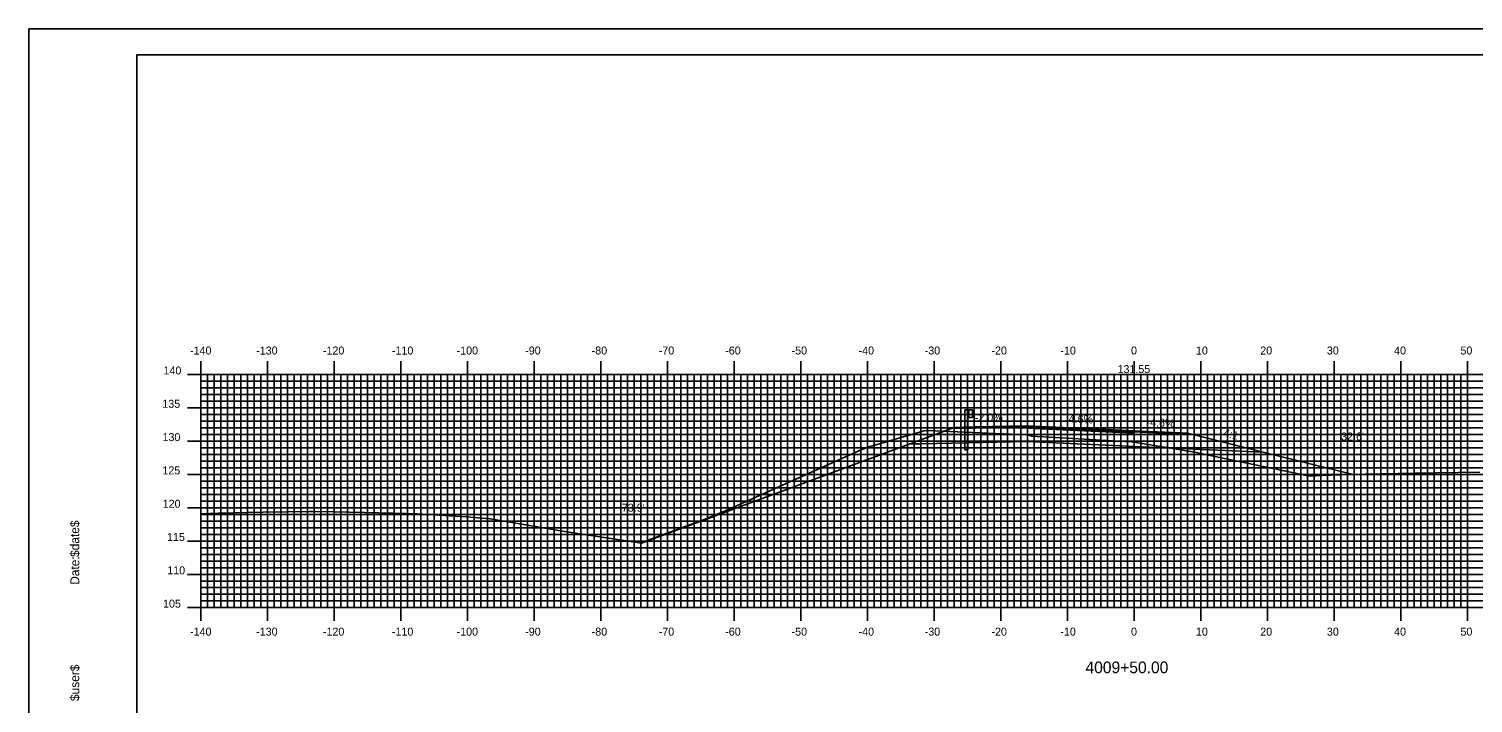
# Model space of a CAD drawing. Extents: x 852147 to 852490, y 364661 to 364881.
# Drawn here: x 852147 to 852363.6, y 364780 to 364881.3 of the extents above; entities that cross this region are included whole.
import ezdxf

# ---------------------------------------------------------------- set-up
doc = ezdxf.new("R2010")
doc.units = 0
for name, color, linetype in [('ANNOTATION', 7, 'Continuous'), ('BORDER', 7, 'Continuous'), ('D_Guardrail_Beam_Lt', 7, 'Continuous'), ('D_Roadway_Centerline_Text', 7, 'Continuous'), ('D_Roadway_Edge_Shoulder', 7, 'Continuous'), ('D_Roadway_Edge_TW', 7, 'Continuous'), ('D_Roadway_Pavement', 7, 'Continuous'), ('D_Roadway_SlopeLines', 7, 'Continuous'), ('D_Roadway_SubGrade', 7, 'Continuous'), ('D_Text_Standard', 7, 'Continuous'), ('H_V ANNOTATION', 7, 'Continuous'), ('M_Roadway_Centerline', 7, 'Continuous'), ('MAJOR', 7, 'Continuous'), ('MINOR', 7, 'Continuous'), ('PLOT BOUNDARY', 7, 'Continuous'), ('S_Roadway_Centerline', 7, 'Continuous')]:
    doc.layers.add(name, color=color, linetype=linetype)

msp = doc.modelspace()

# ---------------------------------------------------------------- linework, layer by layer
at = {"layer": 'ANNOTATION'}
for p, q in [((852285.76, 364821.43), (852238.86, 364804.07)), ((852280.84, 364818.98), (852279.02, 364818.94))]:
    msp.add_line(p, q, dxfattribs=at)
at = {"layer": 'BORDER'}
msp.add_lwpolyline([(852163.16, 364667.37), (852483.16, 364667.37), (852483.16, 364877.37), (852163.16, 364877.37)], close=True, dxfattribs=at)
at = {"layer": 'D_Guardrail_Beam_Lt'}
for p, q in [((852287.33, 364824.08), (852287.33, 364818.08)), ((852287.8, 364824.08), (852287.33, 364824.08)), ((852288.48, 364824.08), (852287.8, 364824.08)), ((852287.8, 364824.08), (852287.8, 364822.91)), ((852287.86, 364824.08), (852287.86, 364822.91)), ((852287.96, 364824.08), (852287.96, 364822.91)), ((852288.48, 364822.91), (852288.48, 364824.08)), ((852288.48, 364823.99), (852288.56, 364823.98)), ((852288.49, 364823.53), (852288.49, 364823.46)), ((852288.72, 364823.73), (852288.52, 364823.59)), ((852288.52, 364823.39), (852288.72, 364823.26)), ((852288.57, 364823.97), (852288.72, 364823.87)), ((852288.72, 364823.11), (852288.57, 364823.01)), ((852287.8, 364822.91), (852288.48, 364822.91)), ((852287.82, 364818.08), (852287.82, 364822.91)), ((852288.56, 364823.01), (852288.48, 364822.99)), ((852287.82, 364818.08), (852287.33, 364818.08))]:
    msp.add_line(p, q, dxfattribs=at)
for centre, major_axis, start_param, end_param in [((852288.57, 364823.53), (-0.0789, 0), 5.323254, 6.283185), ((852288.57, 364823.46), (-0.0789, 0), 6.283185, 7.243116), ((852288.55, 364823.94), (0.0417, 0), 0.959931, 1.376053), ((852288.67, 364823.8), (0.0877, 0), 5.323254, 7.243116), ((852288.67, 364823.19), (0.0877, 0), 5.323254, 7.243116), ((852288.55, 364823.05), (0.0417, 0), 4.907132, 5.323254)]:
    msp.add_ellipse(centre, major_axis=major_axis, ratio=0.995501, start_param=start_param, end_param=end_param, dxfattribs=at)
at = {"layer": 'D_Roadway_Edge_Shoulder'}
msp.add_lwpolyline([(852296.76, 364821.65), (852288.76, 364821.49), (852288.76, 364821.49), (852285.76, 364821.43), (852285.76, 364821.27), (852296.76, 364821.46)], close=True, dxfattribs=at)
at = {"layer": 'D_Roadway_Edge_TW'}
msp.add_line((852312.76, 364820.92), (852320.76, 364820.55), dxfattribs=at)
msp.add_lwpolyline([(852296.76, 364821.65), (852312.76, 364820.92), (852312.76, 364820.75), (852296.76, 364821.47)], close=True, dxfattribs=at)
msp.add_lwpolyline([(852312.76, 364820.75), (852320.76, 364820.38), (852320.76, 364820.55)], dxfattribs=at)
at = {"layer": 'D_Roadway_Pavement'}
msp.add_lwpolyline([(852296.76, 364821.47), (852312.76, 364820.75), (852312.76, 364820.58), (852296.76, 364821.3)], close=True, dxfattribs=at)
for points in [[(852296.76, 364821.47), (852296.76, 364821.3)], [(852312.76, 364820.75), (852312.76, 364820.58)], [(852312.76, 364820.75), (852312.76, 364820.58)]]:
    msp.add_lwpolyline(points, dxfattribs=at)
at = {"layer": 'D_Roadway_SlopeLines'}
msp.add_lwpolyline([(852320.76, 364820.55), (852332.29, 364817.67), (852345.39, 364814.39)], dxfattribs=at)
at = {"layer": 'D_Roadway_SubGrade'}
msp.add_line((852312.76, 364818.58), (852332.05, 364817.72), dxfattribs=at)
msp.add_lwpolyline([(852280.84, 364818.98), (852296.76, 364819.29), (852296.76, 364821.29), (852296.76, 364821.46), (852285.76, 364821.27), (852285.76, 364821.43)], dxfattribs=at)
msp.add_lwpolyline([(852296.76, 364821.3), (852312.76, 364820.58), (852312.76, 364818.58), (852296.76, 364819.3)], close=True, dxfattribs=at)
at = {"layer": 'MAJOR'}
for p, q in [((852172.76, 364831.37), (852172.76, 364829.37)), ((852182.76, 364831.37), (852182.76, 364829.37)), ((852192.76, 364831.37), (852192.76, 364829.37)), ((852202.76, 364831.37), (852202.76, 364829.37)), ((852212.76, 364831.37), (852212.76, 364829.37)), ((852222.76, 364831.37), (852222.76, 364829.37)), ((852232.76, 364831.37), (852232.76, 364829.37)), ((852242.76, 364831.37), (852242.76, 364829.37)), ((852252.76, 364831.37), (852252.76, 364829.37)), ((852262.76, 364831.37), (852262.76, 364829.37)), ((852272.76, 364831.37), (852272.76, 364829.37)), ((852282.76, 364831.37), (852282.76, 364829.37)), ((852292.76, 364831.37), (852292.76, 364829.37)), ((852302.76, 364831.37), (852302.76, 364829.37)), ((852312.76, 364831.37), (852312.76, 364829.37)), ((852322.76, 364831.37), (852322.76, 364829.37)), ((852332.76, 364831.37), (852332.76, 364829.37)), ((852342.76, 364831.37), (852342.76, 364829.37)), ((852352.76, 364831.37), (852352.76, 364829.37)), ((852362.76, 364831.37), (852362.76, 364829.37)), ((852170.75, 364829.37), (852172.76, 364829.37)), ((852172.76, 364829.37), (852452.76, 364829.37)), ((852172.76, 364794.37), (852172.76, 364829.37)), ((852172.76, 364794.37), (852172.76, 364829.37)), ((852172.76, 364829.37), (852452.76, 364829.37)), ((852182.76, 364794.37), (852182.76, 364829.37)), ((852192.76, 364794.37), (852192.76, 364829.37)), ((852202.76, 364794.37), (852202.76, 364829.37)), ((852212.76, 364794.37), (852212.76, 364829.37)), ((852222.76, 364794.37), (852222.76, 364829.37)), ((852232.76, 364794.37), (852232.76, 364829.37)), ((852242.76, 364794.37), (852242.76, 364829.37)), ((852252.76, 364794.37), (852252.76, 364829.37)), ((852262.76, 364794.37), (852262.76, 364829.37)), ((852272.76, 364794.37), (852272.76, 364829.37)), ((852282.76, 364794.37), (852282.76, 364829.37)), ((852292.76, 364794.37), (852292.76, 364829.37)), ((852302.76, 364794.37), (852302.76, 364829.37)), ((852312.76, 364794.37), (852312.76, 364829.37)), ((852322.76, 364794.37), (852322.76, 364829.37)), ((852332.76, 364794.37), (852332.76, 364829.37)), ((852342.76, 364794.37), (852342.76, 364829.37)), ((852352.76, 364794.37), (852352.76, 364829.37)), ((852362.76, 364794.37), (852362.76, 364829.37)), ((852170.75, 364824.37), (852172.76, 364824.37)), ((852172.76, 364824.37), (852452.76, 364824.37)), ((852170.75, 364819.37), (852172.76, 364819.37)), ((852172.76, 364819.37), (852452.76, 364819.37)), ((852170.75, 364814.37), (852172.76, 364814.37)), ((852172.76, 364814.37), (852452.76, 364814.37)), ((852170.75, 364809.37), (852172.76, 364809.37)), ((852172.76, 364809.37), (852452.76, 364809.37)), ((852170.75, 364804.37), (852172.76, 364804.37)), ((852172.76, 364804.37), (852452.76, 364804.37)), ((852170.75, 364799.37), (852172.76, 364799.37)), ((852172.76, 364799.37), (852452.76, 364799.37)), ((852170.75, 364794.37), (852172.76, 364794.37)), ((852172.76, 364794.37), (852452.76, 364794.37)), ((852172.76, 364794.37), (852452.76, 364794.37)), ((852172.76, 364792.37), (852172.76, 364794.37)), ((852182.76, 364792.37), (852182.76, 364794.37)), ((852192.76, 364792.37), (852192.76, 364794.37)), ((852202.76, 364792.37), (852202.76, 364794.37)), ((852212.76, 364792.37), (852212.76, 364794.37)), ((852222.76, 364792.37), (852222.76, 364794.37)), ((852232.76, 364792.37), (852232.76, 364794.37)), ((852242.76, 364792.37), (852242.76, 364794.37)), ((852252.76, 364792.37), (852252.76, 364794.37)), ((852262.76, 364792.37), (852262.76, 364794.37)), ((852272.76, 364792.37), (852272.76, 364794.37)), ((852282.76, 364792.37), (852282.76, 364794.37)), ((852292.76, 364792.37), (852292.76, 364794.37)), ((852302.76, 364792.37), (852302.76, 364794.37)), ((852312.76, 364792.37), (852312.76, 364794.37)), ((852322.76, 364792.37), (852322.76, 364794.37)), ((852332.76, 364792.37), (852332.76, 364794.37)), ((852342.76, 364792.37), (852342.76, 364794.37)), ((852352.76, 364792.37), (852352.76, 364794.37)), ((852362.76, 364792.37), (852362.76, 364794.37))]:
    msp.add_line(p, q, dxfattribs=at)
at = {"layer": 'MINOR'}
for p, q in [((852172.76, 364828.37), (852452.76, 364828.37)), ((852172.76, 364828.37), (852174.76, 364828.37)), ((852172.76, 364827.37), (852452.76, 364827.37)), ((852172.76, 364827.37), (852174.76, 364827.37)), ((852173.76, 364794.37), (852173.76, 364829.37)), ((852174.76, 364794.37), (852174.76, 364829.37)), ((852175.76, 364794.37), (852175.76, 364829.37)), ((852176.76, 364794.37), (852176.76, 364829.37)), ((852177.76, 364794.37), (852177.76, 364829.37)), ((852178.76, 364794.37), (852178.76, 364829.37)), ((852179.76, 364794.37), (852179.76, 364829.37)), ((852180.76, 364794.37), (852180.76, 364829.37)), ((852181.76, 364794.37), (852181.76, 364829.37)), ((852183.76, 364794.37), (852183.76, 364829.37)), ((852184.76, 364794.37), (852184.76, 364829.37)), ((852185.76, 364794.37), (852185.76, 364829.37)), ((852186.76, 364794.37), (852186.76, 364829.37)), ((852187.76, 364794.37), (852187.76, 364829.37)), ((852188.76, 364794.37), (852188.76, 364829.37)), ((852189.76, 364794.37), (852189.76, 364829.37)), ((852190.76, 364794.37), (852190.76, 364829.37)), ((852191.76, 364794.37), (852191.76, 364829.37)), ((852193.76, 364794.37), (852193.76, 364829.37)), ((852194.76, 364794.37), (852194.76, 364829.37)), ((852195.76, 364794.37), (852195.76, 364829.37)), ((852196.76, 364794.37), (852196.76, 364829.37)), ((852197.76, 364794.37), (852197.76, 364829.37)), ((852198.76, 364794.37), (852198.76, 364829.37)), ((852199.76, 364794.37), (852199.76, 364829.37)), ((852200.76, 364794.37), (852200.76, 364829.37)), ((852201.76, 364794.37), (852201.76, 364829.37)), ((852203.76, 364794.37), (852203.76, 364829.37)), ((852204.76, 364794.37), (852204.76, 364829.37)), ((852205.76, 364794.37), (852205.76, 364829.37)), ((852206.76, 364794.37), (852206.76, 364829.37)), ((852207.76, 364794.37), (852207.76, 364829.37)), ((852208.76, 364794.37), (852208.76, 364829.37)), ((852209.76, 364794.37), (852209.76, 364829.37)), ((852210.76, 364794.37), (852210.76, 364829.37)), ((852211.76, 364794.37), (852211.76, 364829.37)), ((852213.76, 364794.37), (852213.76, 364829.37)), ((852214.76, 364794.37), (852214.76, 364829.37)), ((852215.76, 364794.37), (852215.76, 364829.37)), ((852216.76, 364794.37), (852216.76, 364829.37)), ((852217.76, 364794.37), (852217.76, 364829.37)), ((852218.76, 364794.37), (852218.76, 364829.37)), ((852219.76, 364794.37), (852219.76, 364829.37)), ((852220.76, 364794.37), (852220.76, 364829.37)), ((852221.76, 364794.37), (852221.76, 364829.37)), ((852223.76, 364794.37), (852223.76, 364829.37)), ((852224.76, 364794.37), (852224.76, 364829.37)), ((852225.76, 364794.37), (852225.76, 364829.37)), ((852226.76, 364794.37), (852226.76, 364829.37)), ((852227.76, 364794.37), (852227.76, 364829.37)), ((852228.76, 364794.37), (852228.76, 364829.37)), ((852229.76, 364794.37), (852229.76, 364829.37)), ((852230.76, 364794.37), (852230.76, 364829.37)), ((852231.76, 364794.37), (852231.76, 364829.37)), ((852233.76, 364794.37), (852233.76, 364829.37)), ((852234.76, 364794.37), (852234.76, 364829.37)), ((852235.76, 364794.37), (852235.76, 364829.37)), ((852236.76, 364794.37), (852236.76, 364829.37)), ((852237.76, 364794.37), (852237.76, 364829.37)), ((852238.76, 364794.37), (852238.76, 364829.37)), ((852239.76, 364794.37), (852239.76, 364829.37)), ((852240.76, 364794.37), (852240.76, 364829.37)), ((852241.76, 364794.37), (852241.76, 364829.37)), ((852243.76, 364794.37), (852243.76, 364829.37)), ((852244.76, 364794.37), (852244.76, 364829.37)), ((852245.76, 364794.37), (852245.76, 364829.37)), ((852246.76, 364794.37), (852246.76, 364829.37)), ((852247.76, 364794.37), (852247.76, 364829.37)), ((852248.76, 364794.37), (852248.76, 364829.37)), ((852249.76, 364794.37), (852249.76, 364829.37)), ((852250.76, 364794.37), (852250.76, 364829.37)), ((852251.76, 364794.37), (852251.76, 364829.37)), ((852253.76, 364794.37), (852253.76, 364829.37)), ((852254.76, 364794.37), (852254.76, 364829.37)), ((852255.76, 364794.37), (852255.76, 364829.37)), ((852256.76, 364794.37), (852256.76, 364829.37)), ((852257.76, 364794.37), (852257.76, 364829.37)), ((852258.76, 364794.37), (852258.76, 364829.37)), ((852259.76, 364794.37), (852259.76, 364829.37)), ((852260.76, 364794.37), (852260.76, 364829.37)), ((852261.76, 364794.37), (852261.76, 364829.37)), ((852263.76, 364794.37), (852263.76, 364829.37)), ((852264.76, 364794.37), (852264.76, 364829.37)), ((852265.76, 364794.37), (852265.76, 364829.37)), ((852266.76, 364794.37), (852266.76, 364829.37)), ((852267.76, 364794.37), (852267.76, 364829.37)), ((852268.76, 364794.37), (852268.76, 364829.37)), ((852269.76, 364794.37), (852269.76, 364829.37)), ((852270.76, 364794.37), (852270.76, 364829.37)), ((852271.76, 364794.37), (852271.76, 364829.37)), ((852273.76, 364794.37), (852273.76, 364829.37)), ((852274.76, 364794.37), (852274.76, 364829.37)), ((852275.76, 364794.37), (852275.76, 364829.37)), ((852276.76, 364794.37), (852276.76, 364829.37)), ((852277.76, 364794.37), (852277.76, 364829.37)), ((852278.76, 364794.37), (852278.76, 364829.37)), ((852279.76, 364794.37), (852279.76, 364829.37)), ((852280.76, 364794.37), (852280.76, 364829.37)), ((852281.76, 364794.37), (852281.76, 364829.37)), ((852283.76, 364794.37), (852283.76, 364829.37)), ((852284.76, 364794.37), (852284.76, 364829.37)), ((852285.76, 364794.37), (852285.76, 364829.37)), ((852286.76, 364794.37), (852286.76, 364829.37)), ((852287.76, 364794.37), (852287.76, 364829.37)), ((852288.76, 364794.37), (852288.76, 364829.37)), ((852289.76, 364794.37), (852289.76, 364829.37)), ((852290.76, 364794.37), (852290.76, 364829.37)), ((852291.76, 364794.37), (852291.76, 364829.37)), ((852293.76, 364794.37), (852293.76, 364829.37)), ((852294.76, 364794.37), (852294.76, 364829.37)), ((852295.76, 364794.37), (852295.76, 364829.37)), ((852296.76, 364794.37), (852296.76, 364829.37)), ((852297.76, 364794.37), (852297.76, 364829.37)), ((852298.76, 364794.37), (852298.76, 364829.37)), ((852299.76, 364794.37), (852299.76, 364829.37)), ((852300.76, 364794.37), (852300.76, 364829.37)), ((852301.76, 364794.37), (852301.76, 364829.37)), ((852303.76, 364794.37), (852303.76, 364829.37)), ((852304.76, 364794.37), (852304.76, 364829.37)), ((852305.76, 364794.37), (852305.76, 364829.37)), ((852306.76, 364794.37), (852306.76, 364829.37)), ((852307.76, 364794.37), (852307.76, 364829.37)), ((852308.76, 364794.37), (852308.76, 364829.37)), ((852309.76, 364794.37), (852309.76, 364829.37)), ((852310.76, 364794.37), (852310.76, 364829.37)), ((852311.76, 364794.37), (852311.76, 364829.37)), ((852313.76, 364794.37), (852313.76, 364829.37)), ((852314.76, 364794.37), (852314.76, 364829.37)), ((852315.76, 364794.37), (852315.76, 364829.37)), ((852316.76, 364794.37), (852316.76, 364829.37)), ((852317.76, 364794.37), (852317.76, 364829.37)), ((852318.76, 364794.37), (852318.76, 364829.37)), ((852319.76, 364794.37), (852319.76, 364829.37)), ((852320.76, 364794.37), (852320.76, 364829.37)), ((852321.76, 364794.37), (852321.76, 364829.37)), ((852323.76, 364794.37), (852323.76, 364829.37)), ((852324.76, 364794.37), (852324.76, 364829.37)), ((852325.76, 364794.37), (852325.76, 364829.37)), ((852326.76, 364794.37), (852326.76, 364829.37)), ((852327.76, 364794.37), (852327.76, 364829.37)), ((852328.76, 364794.37), (852328.76, 364829.37)), ((852329.76, 364794.37), (852329.76, 364829.37)), ((852330.76, 364794.37), (852330.76, 364829.37)), ((852331.76, 364794.37), (852331.76, 364829.37)), ((852333.76, 364794.37), (852333.76, 364829.37)), ((852334.76, 364794.37), (852334.76, 364829.37)), ((852335.76, 364794.37), (852335.76, 364829.37)), ((852336.76, 364794.37), (852336.76, 364829.37)), ((852337.76, 364794.37), (852337.76, 364829.37)), ((852338.76, 364794.37), (852338.76, 364829.37)), ((852339.76, 364794.37), (852339.76, 364829.37)), ((852340.76, 364794.37), (852340.76, 364829.37)), ((852341.76, 364794.37), (852341.76, 364829.37)), ((852343.76, 364794.37), (852343.76, 364829.37)), ((852344.76, 364794.37), (852344.76, 364829.37)), ((852345.76, 364794.37), (852345.76, 364829.37)), ((852346.76, 364794.37), (852346.76, 364829.37)), ((852347.76, 364794.37), (852347.76, 364829.37)), ((852348.76, 364794.37), (852348.76, 364829.37)), ((852349.76, 364794.37), (852349.76, 364829.37)), ((852350.76, 364794.37), (852350.76, 364829.37)), ((852351.76, 364794.37), (852351.76, 364829.37)), ((852353.76, 364794.37), (852353.76, 364829.37)), ((852354.76, 364794.37), (852354.76, 364829.37)), ((852355.76, 364794.37), (852355.76, 364829.37)), ((852356.76, 364794.37), (852356.76, 364829.37)), ((852357.76, 364794.37), (852357.76, 364829.37)), ((852358.76, 364794.37), (852358.76, 364829.37)), ((852359.76, 364794.37), (852359.76, 364829.37)), ((852360.76, 364794.37), (852360.76, 364829.37)), ((852361.76, 364794.37), (852361.76, 364829.37)), ((852172.76, 364826.37), (852452.76, 364826.37)), ((852172.76, 364826.37), (852174.76, 364826.37)), ((852172.76, 364825.37), (852452.76, 364825.37)), ((852172.76, 364825.37), (852174.76, 364825.37)), ((852172.76, 364823.37), (852452.76, 364823.37)), ((852172.76, 364823.37), (852174.76, 364823.37)), ((852172.76, 364822.37), (852452.76, 364822.37)), ((852172.76, 364822.37), (852174.76, 364822.37)), ((852172.76, 364821.37), (852452.76, 364821.37)), ((852172.76, 364821.37), (852174.76, 364821.37)), ((852172.76, 364820.37), (852452.76, 364820.37)), ((852172.76, 364820.37), (852174.76, 364820.37)), ((852172.76, 364818.37), (852452.76, 364818.37)), ((852172.76, 364818.37), (852174.76, 364818.37)), ((852172.76, 364817.37), (852452.76, 364817.37)), ((852172.76, 364817.37), (852174.76, 364817.37)), ((852172.76, 364816.37), (852452.76, 364816.37)), ((852172.76, 364816.37), (852174.76, 364816.37)), ((852172.76, 364815.37), (852452.76, 364815.37)), ((852172.76, 364815.37), (852174.76, 364815.37)), ((852172.76, 364813.37), (852452.76, 364813.37)), ((852172.76, 364813.37), (852174.76, 364813.37)), ((852172.76, 364812.37), (852452.76, 364812.37)), ((852172.76, 364812.37), (852174.76, 364812.37)), ((852172.76, 364811.37), (852452.76, 364811.37)), ((852172.76, 364811.37), (852174.76, 364811.37)), ((852172.76, 364810.37), (852452.76, 364810.37)), ((852172.76, 364810.37), (852174.76, 364810.37)), ((852172.76, 364808.37), (852452.76, 364808.37)), ((852172.76, 364808.37), (852174.76, 364808.37)), ((852172.76, 364807.37), (852452.76, 364807.37)), ((852172.76, 364807.37), (852174.76, 364807.37)), ((852172.76, 364806.37), (852452.76, 364806.37)), ((852172.76, 364806.37), (852174.76, 364806.37)), ((852172.76, 364805.37), (852452.76, 364805.37)), ((852172.76, 364805.37), (852174.76, 364805.37)), ((852172.76, 364803.37), (852452.76, 364803.37)), ((852172.76, 364803.37), (852174.76, 364803.37)), ((852172.76, 364802.37), (852452.76, 364802.37)), ((852172.76, 364802.37), (852174.76, 364802.37)), ((852172.76, 364801.37), (852452.76, 364801.37)), ((852172.76, 364801.37), (852174.76, 364801.37)), ((852172.76, 364800.37), (852452.76, 364800.37)), ((852172.76, 364800.37), (852174.76, 364800.37)), ((852172.76, 364798.37), (852452.76, 364798.37)), ((852172.76, 364798.37), (852174.76, 364798.37)), ((852172.76, 364797.37), (852452.76, 364797.37)), ((852172.76, 364797.37), (852174.76, 364797.37)), ((852172.76, 364796.37), (852452.76, 364796.37)), ((852172.76, 364796.37), (852174.76, 364796.37)), ((852172.76, 364795.37), (852452.76, 364795.37)), ((852172.76, 364795.37), (852174.76, 364795.37))]:
    msp.add_line(p, q, dxfattribs=at)
at = {"layer": 'PLOT BOUNDARY'}
msp.add_lwpolyline([(852146.97, 364661.25), (852486.97, 364661.25), (852486.97, 364881.25), (852146.97, 364881.25)], close=True, dxfattribs=at)
at = {"layer": 'S_Roadway_Centerline'}
msp.add_lwpolyline([(852172.76, 364808.46), (852175.37, 364808.53), (852182.11, 364808.72), (852189.05, 364808.82), (852189.49, 364808.79), (852192.81, 364808.74), (852201.72, 364808.55), (852205.2, 364808.43), (852211.75, 364808.03), (852212.57, 364807.99), (852216.15, 364807.71), (852227.32, 364805.8), (852229.94, 364805.4), (852238.86, 364804.07), (852238.86, 364804.18), (852238.9, 364804.14), (852248.4, 364807.65), (852251.57, 364808.95), (852271.88, 364818.11), (852273.15, 364818.55), (852281.4, 364820.96), (852282.81, 364820.92), (852291.97, 364820.51), (852296.67, 364820.29), (852297.25, 364820.14), (852297.27, 364820.14), (852297.38, 364820.13), (852311.35, 364819.3), (852312.46, 364819.27), (852321.81, 364817.72), (852322.06, 364817.66), (852323.87, 364817.28), (852337.87, 364814.34), (852338.96, 364814.09), (852340.92, 364814.2), (852344.88, 364814.38), (852354.84, 364814.54), (852364.58, 364814.72)], dxfattribs=at)

# ---------------------------------------------------------------- texts
at = {"layer": 'ANNOTATION'}
for s, rotation, p in [('-2.0%', 1.1458, (852288.86, 364822.3)), ('4.6%', 357.3663, (852302.9, 364822.17)), ('-4.6%', 357.3663, (852314.58, 364821.64)), ('4:1', 345.9638, (852326.03, 364820.09))]:
    msp.add_text(s, height=1.2, rotation=rotation, dxfattribs=at).set_placement(p)
at = {"layer": 'BORDER'}
for s, p in [('$date$', (852154.52, 364801.98)), ('Date:', (852154.52, 364797.8)), ('$user$', (852154.52, 364780.35))]:
    msp.add_text(s, height=1.339, rotation=90, dxfattribs=at).set_placement(p)
at = {"layer": 'D_Roadway_Centerline_Text'}
msp.add_text('131.55', height=1.2, dxfattribs=at).set_placement((852310.25, 364829.58))
at = {"layer": 'D_Text_Standard'}
for s, p in [("32.6'", (852343.78, 364819.46)), ("73.9'", (852235.9, 364808.78))]:
    msp.add_text(s, height=1.2, dxfattribs=at).set_placement(p)
at = {"layer": 'H_V ANNOTATION'}
for s, height, p in [('-140', 1.2, (852171.14, 364832.37)), ('-130', 1.2, (852181.06, 364832.37)), ('-120', 1.2, (852191.07, 364832.37)), ('-110', 1.2, (852201.42, 364832.37)), ('-100', 1.2, (852211.12, 364832.37)), ('-90', 1.2, (852221.41, 364832.37)), ('-80', 1.2, (852231.38, 364832.37)), ('-70', 1.2, (852241.44, 364832.37)), ('-60', 1.2, (852251.41, 364832.37)), ('-50', 1.2, (852261.36, 364832.37)), ('-40', 1.2, (852271.41, 364832.37)), ('-30', 1.2, (852281.33, 364832.37)), ('-20', 1.2, (852291.34, 364832.37)), ('-10', 1.2, (852301.68, 364832.37)), ('0', 1.2, (852312.27, 364832.37)), ('10', 1.2, (852322.01, 364832.37)), ('20', 1.2, (852331.66, 364832.37)), ('30', 1.2, (852341.65, 364832.37)), ('40', 1.2, (852351.73, 364832.37)), ('50', 1.2, (852361.68, 364832.37)), ('140', 1.2, (852167.16, 364829.37)), ('135', 1.2, (852166.98, 364824.37)), ('130', 1.2, (852167.01, 364819.37)), ('125', 1.2, (852167, 364814.37)), ('120', 1.2, (852167.04, 364809.37)), ('115', 1.2, (852167.69, 364804.37)), ('110', 1.2, (852167.72, 364799.37)), ('105', 1.2, (852167.09, 364794.37)), ('-140', 1.2, (852171.14, 364790.17)), ('-130', 1.2, (852181.06, 364790.17)), ('-120', 1.2, (852191.07, 364790.17)), ('-110', 1.2, (852201.42, 364790.17)), ('-100', 1.2, (852211.12, 364790.17)), ('-90', 1.2, (852221.41, 364790.17)), ('-80', 1.2, (852231.38, 364790.17)), ('-70', 1.2, (852241.44, 364790.17)), ('-60', 1.2, (852251.41, 364790.17)), ('-50', 1.2, (852261.36, 364790.17)), ('-40', 1.2, (852271.41, 364790.17)), ('-30', 1.2, (852281.33, 364790.17)), ('-20', 1.2, (852291.34, 364790.17)), ('-10', 1.2, (852301.68, 364790.17)), ('0', 1.2, (852312.27, 364790.17)), ('10', 1.2, (852322.01, 364790.17)), ('20', 1.2, (852331.66, 364790.17)), ('30', 1.2, (852341.65, 364790.17)), ('40', 1.2, (852351.73, 364790.17)), ('50', 1.2, (852361.68, 364790.17)), ('4009+50.00', 1.75, (852305.44, 364784.53))]:
    msp.add_text(s, height=height, dxfattribs=at).set_placement(p)
at = {"layer": 'M_Roadway_Centerline'}
for s, p in [('C', (852296.67, 364820.29)), ('L', (852296.67, 364820.28)), ('C', (852189.05, 364808.82)), ('L', (852189.05, 364808.81))]:
    msp.add_text(s, height=0.0146, dxfattribs=at).set_placement(p)
at = {"layer": 'MAJOR'}
msp.add_text('-', height=0.012, dxfattribs=at).set_placement((852172.75, 364794.37))

doc.saveas('drawing.dxf')
